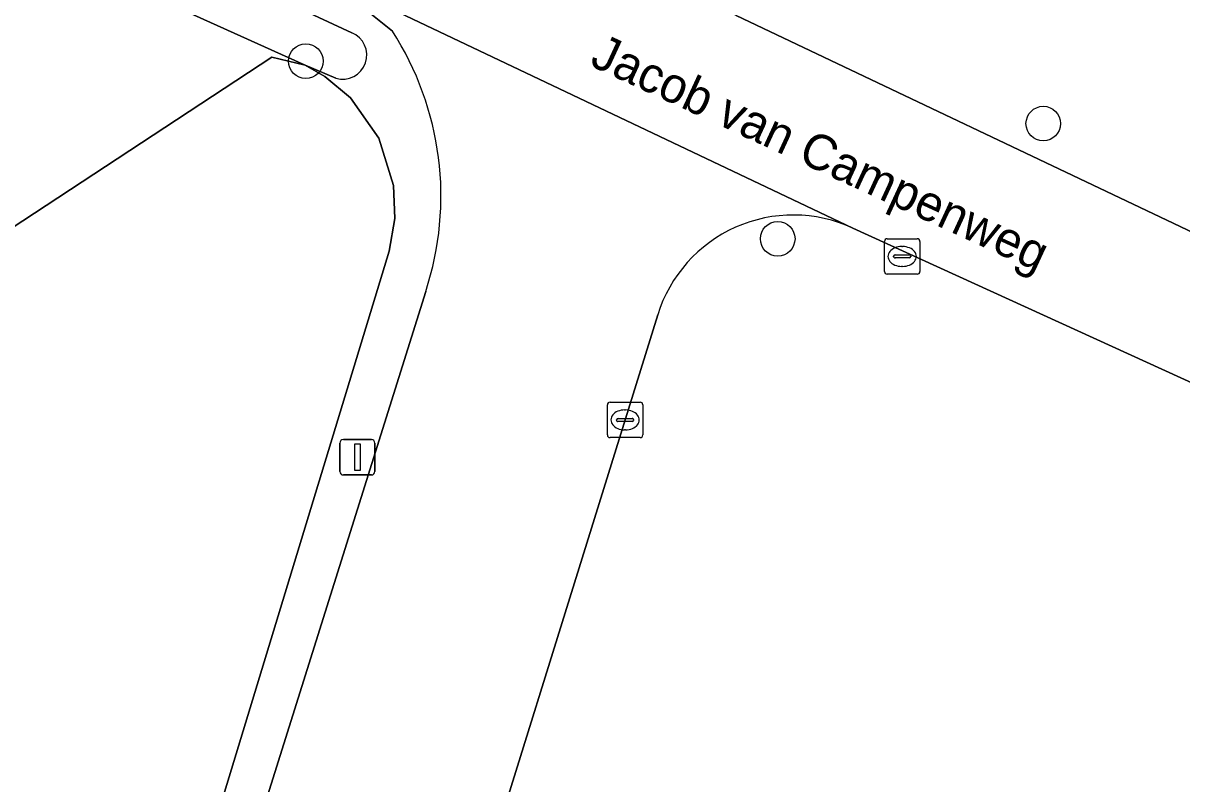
# Model space of a CAD drawing. Extents: x 159352 to 160617, y 385888 to 387323.
# Drawn here: x 159458.49 to 159491.2, y 386468.96 to 386490.44 of the extents above; entities that cross this region are included whole.
import ezdxf

# ---------------------------------------------------------------- set-up
doc = ezdxf.new("R2010")
doc.units = 0
for name, color, linetype in [('IMGEO_Boom', 7, 'Continuous'), ('IMGEO_Erf', 7, 'Continuous'), ('IMGEO_Fietspad_gesloten', 7, 'Continuous'), ('IMGEO_Groenvoorziening', 7, 'Continuous'), ('IMGEO_Hek', 7, 'Continuous'), ('IMGEO_Kolk', 7, 'Continuous'), ('IMGEO_Lichtmast', 7, 'Continuous'), ('IMGEO_Openbare_ruimte_label', 7, 'Continuous'), ('IMGEO_Parkeervlak_halfverhard', 7, 'Continuous'), ('IMGEO_Rijbaan_lokaal_open', 7, 'Continuous'), ('IMGEO_Voetpad_onverhard', 7, 'Continuous'), ('IMGEO_Waterloop', 7, 'Continuous')]:
    doc.layers.add(name, color=color, linetype=linetype)

msp = doc.modelspace()

# ---------------------------------------------------------------- linework, layer by layer
at = {"layer": 'IMGEO_Boom'}
for centre in [(159466.465, 386489.367), (159487.286, 386487.602), (159479.787, 386484.351)]:
    msp.add_circle(centre, 0.489, dxfattribs=at)
at = {"layer": 'IMGEO_Erf'}
msp.add_lwpolyline([(159438.145, 386502.052), (159394.408, 386443.649), (159395.776, 386444.526), (159396.765, 386445.16), (159400.178, 386447.348), (159422.814, 386461.343), (159428.157, 386464.835), (159428.019, 386465.117), (159429.657, 386465.92), (159465.501, 386489.478), (159466.443, 386489.251), (159459.951, 386492.191), (159454.7, 386494.569), (159449.452, 386496.945), (159443.774, 386499.56), (159442.776, 386500), (159439.685, 386501.364), (159438.638, 386501.832), (159438.384, 386501.945), (159438.145, 386502.052), (159438.145, 386502.052)], dxfattribs=at)
at = {"layer": 'IMGEO_Fietspad_gesloten'}
msp.add_lwpolyline([(159454.66, 386497.595), (159460.09, 386495.022), (159467.031, 386491.732), (159481.905, 386484.652), (159500, 386476.402), (159515.978, 386469.117), (159517.402, 386472.271), (159510.81, 386475.39), (159510.308, 386475.628), (159491.723, 386484.422), (159478.618, 386490.659), (159470.08, 386494.703), (159467.828, 386495.766), (159458.854, 386500), (159442.597, 386507.622)], dxfattribs=at)
at = {"layer": 'IMGEO_Groenvoorziening'}
for points in [[(159468.91, 386490.217), (159467.031, 386491.732), (159466.566, 386490.717), (159467.76, 386490.17)], [(159467.314, 386488.885), (159466.443, 386489.251), (159467.005, 386488.931), (159467.722, 386488.334), (159468.528, 386487.192), (159468.942, 386485.857), (159468.978, 386484.923), (159468.819, 386484.003), (159460.775, 386457.568), (159460.504, 386454.825), (159460.866, 386452.718), (159463.993, 386447.575)], [(159463.152, 386461.523), (159469.852, 386482.865)]]:
    msp.add_lwpolyline(points, dxfattribs=at)
msp.add_lwpolyline([(159468.819, 386484.003), (159468.978, 386484.923), (159468.942, 386485.857), (159468.528, 386487.192), (159467.722, 386488.334), (159467.005, 386488.931), (159466.443, 386489.251), (159465.501, 386489.478), (159429.657, 386465.92), (159437.872, 386469.949), (159439.272, 386467.094), (159429.419, 386462.262), (159429.146, 386462.818), (159427.415, 386461.686), (159437.125, 386443.389), (159450.601, 386448.684), (159460.866, 386452.718), (159460.504, 386454.825), (159460.775, 386457.568)], close=True, dxfattribs=at)
for centre, radius, start, end in [((159467.504, 386489.539), 0.681, 253.8382, 67.8799), ((159461.665, 386485.552), 8.616, 341.8268, 32.7761)]:
    msp.add_arc(centre, radius, start, end, dxfattribs=at)
at = {"layer": 'IMGEO_Hek'}
msp.add_lwpolyline([(159466.443, 386489.251), (159465.501, 386489.478), (159426.329, 386463.733)], dxfattribs=at)
at = {"layer": 'IMGEO_Kolk'}
for p, q in [((159482.801, 386483.426), (159482.801, 386484.278)), ((159482.876, 386484.352), (159483.728, 386484.352)), ((159483.289, 386484.132), (159483.314, 386484.132)), ((159483.802, 386484.278), (159483.802, 386483.426)), ((159483.06, 386483.846), (159483.06, 386483.858)), ((159483.498, 386483.809), (159483.1, 386483.809)), ((159483.103, 386483.895), (159483.501, 386483.895)), ((159483.544, 386483.858), (159483.544, 386483.846)), ((159483.312, 386483.572), (159483.287, 386483.572)), ((159483.728, 386483.352), (159482.876, 386483.352)), ((159474.978, 386478.812), (159474.978, 386479.664)), ((159475.053, 386479.738), (159475.905, 386479.738)), ((159475.466, 386479.518), (159475.491, 386479.518)), ((159475.979, 386479.664), (159475.979, 386478.812)), ((159475.237, 386479.232), (159475.237, 386479.244)), ((159475.675, 386479.195), (159475.277, 386479.195)), ((159475.28, 386479.281), (159475.678, 386479.281)), ((159475.721, 386479.244), (159475.721, 386479.232)), ((159475.489, 386478.958), (159475.464, 386478.958)), ((159475.905, 386478.738), (159475.053, 386478.738))]:
    msp.add_line(p, q, dxfattribs=at)
for points in [[(159482.801, 386483.426), (159482.801, 386484.278)], [(159482.876, 386484.352), (159483.728, 386484.352)], [(159483.802, 386484.278), (159483.802, 386483.426)], [(159483.728, 386483.352), (159482.876, 386483.352)], [(159474.978, 386478.812), (159474.978, 386479.664)], [(159475.053, 386479.738), (159475.905, 386479.738)], [(159475.979, 386479.664), (159475.979, 386478.812)], [(159475.905, 386478.738), (159475.053, 386478.738)]]:
    msp.add_lwpolyline(points, dxfattribs=at)
for centre, radius, start, end in [((159482.878, 386484.276), 0.0765, 91.552, 178.448), ((159482.878, 386484.276), 0.0765, 91.552, 178.448), ((159483.726, 386484.276), 0.0765, 1.552, 88.448), ((159483.726, 386484.276), 0.0765, 1.552, 88.448), ((159483.1, 386483.855), 0.0403, 85.8775, 175.7526), ((159483.097, 386483.845), 0.0366, 178.938, 274.7102), ((159483.501, 386483.852), 0.043, 264.8664, 352.4533), ((159483.505, 386483.857), 0.0386, 1.7309, 96.639), ((159482.878, 386483.428), 0.0765, 181.552, 268.448), ((159482.878, 386483.428), 0.0765, 181.552, 268.448), ((159483.726, 386483.428), 0.0765, 271.552, 358.448), ((159483.726, 386483.428), 0.0765, 271.552, 358.448), ((159475.055, 386479.662), 0.0765, 91.552, 178.448), ((159475.055, 386479.662), 0.0765, 91.552, 178.448), ((159475.903, 386479.662), 0.0765, 1.552, 88.448), ((159475.903, 386479.662), 0.0765, 1.552, 88.448), ((159475.277, 386479.241), 0.0403, 85.8775, 175.7526), ((159475.274, 386479.231), 0.0366, 178.938, 274.7102), ((159475.678, 386479.238), 0.043, 264.8664, 352.4533), ((159475.682, 386479.243), 0.0386, 1.7309, 96.639), ((159475.055, 386478.814), 0.0765, 181.552, 268.448), ((159475.055, 386478.814), 0.0765, 181.552, 268.448), ((159475.903, 386478.814), 0.0765, 271.552, 358.448), ((159475.903, 386478.814), 0.0765, 271.552, 358.448)]:
    msp.add_arc(centre, radius, start, end, dxfattribs=at)
for centre, major_axis, ratio, start_param, end_param in [((159483.288, 386483.852), (-0.387, 0.002), 0.722429, 4.712389, 7.853982), ((159483.313, 386483.852), (-0.39, 0.002), 0.717154, 1.570796, 4.712389), ((159475.465, 386479.238), (-0.387, 0.002), 0.722429, 4.712389, 7.853982), ((159475.49, 386479.238), (-0.39, 0.002), 0.717154, 1.570796, 4.712389)]:
    msp.add_ellipse(centre, major_axis=major_axis, ratio=ratio, start_param=start_param, end_param=end_param, dxfattribs=at)
at = {"layer": 'IMGEO_Lichtmast'}
for p, q in [((159467.425, 386477.783), (159467.425, 386478.583)), ((159467.425, 386478.583), (159467.425, 386477.783)), ((159467.525, 386478.683), (159468.315, 386478.683)), ((159468.315, 386478.683), (159467.525, 386478.683)), ((159468.415, 386478.583), (159468.415, 386477.783)), ((159468.415, 386477.783), (159468.415, 386478.583)), ((159468.315, 386477.683), (159467.525, 386477.683)), ((159467.525, 386477.683), (159468.315, 386477.683))]:
    msp.add_line(p, q, dxfattribs=at)
msp.add_lwpolyline([(159467.845, 386478.558), (159467.995, 386478.558), (159467.995, 386477.808), (159467.845, 386477.808), (159467.845, 386478.558)], dxfattribs=at)
for centre, start, end in [((159467.525, 386478.583), 90, 180), ((159467.525, 386478.583), 90, 180), ((159468.315, 386478.583), 0, 90), ((159468.315, 386478.583), 360, 90), ((159467.525, 386477.783), 180, 270), ((159467.525, 386477.783), 180, 270), ((159468.315, 386477.783), 270, 0), ((159468.315, 386477.783), 270, 0)]:
    msp.add_arc(centre, 0.1, start, end, dxfattribs=at)
at = {"layer": 'IMGEO_Parkeervlak_halfverhard'}
msp.add_lwpolyline([(159476.399, 386482.204), (159469.559, 386460.205), (159477.671, 386447.442), (159495.539, 386462.217), (159502.941, 386456.606), (159515.761, 386467.917), (159515.863, 386468.007), (159515.978, 386469.117), (159500, 386476.402), (159481.905, 386484.652)], dxfattribs=at)
msp.add_arc((159480.225, 386481.016), 4.006, 65.1967, 162.7437, dxfattribs=at)
at = {"layer": 'IMGEO_Rijbaan_lokaal_open'}
for points in [[(159481.905, 386484.652), (159467.031, 386491.732), (159468.91, 386490.217)], [(159469.852, 386482.865), (159463.152, 386461.523)], [(159469.559, 386460.205), (159476.399, 386482.204)]]:
    msp.add_lwpolyline(points, dxfattribs=at)
for centre, radius, start, end in [((159461.665, 386485.552), 8.616, 341.8268, 32.7761), ((159480.225, 386481.016), 4.006, 65.1967, 162.7437)]:
    msp.add_arc(centre, radius, start, end, dxfattribs=at)
at = {"layer": 'IMGEO_Voetpad_onverhard'}
msp.add_lwpolyline([(159500, 386489.012), (159486.937, 386496.95), (159482.111, 386493.232), (159479.443, 386493.701), (159478.618, 386490.659), (159491.723, 386484.422), (159510.308, 386475.628), (159510.374, 386475.983), (159511.521, 386482.123)], close=True, dxfattribs=at)
at = {"layer": 'IMGEO_Waterloop'}
msp.add_lwpolyline([(159467.76, 386490.17), (159466.566, 386490.717), (159460.067, 386493.693), (159459.951, 386492.191), (159466.443, 386489.251), (159467.314, 386488.885)], dxfattribs=at)
msp.add_arc((159467.504, 386489.539), 0.681, 253.8382, 67.8799, dxfattribs=at)

# ---------------------------------------------------------------- texts
at = {"layer": 'IMGEO_Openbare_ruimte_label'}
msp.add_text('Jacob van Campenweg', height=1, rotation=335.2289, dxfattribs=at).set_placement((159474.447, 386489.259))

doc.saveas('drawing.dxf')
